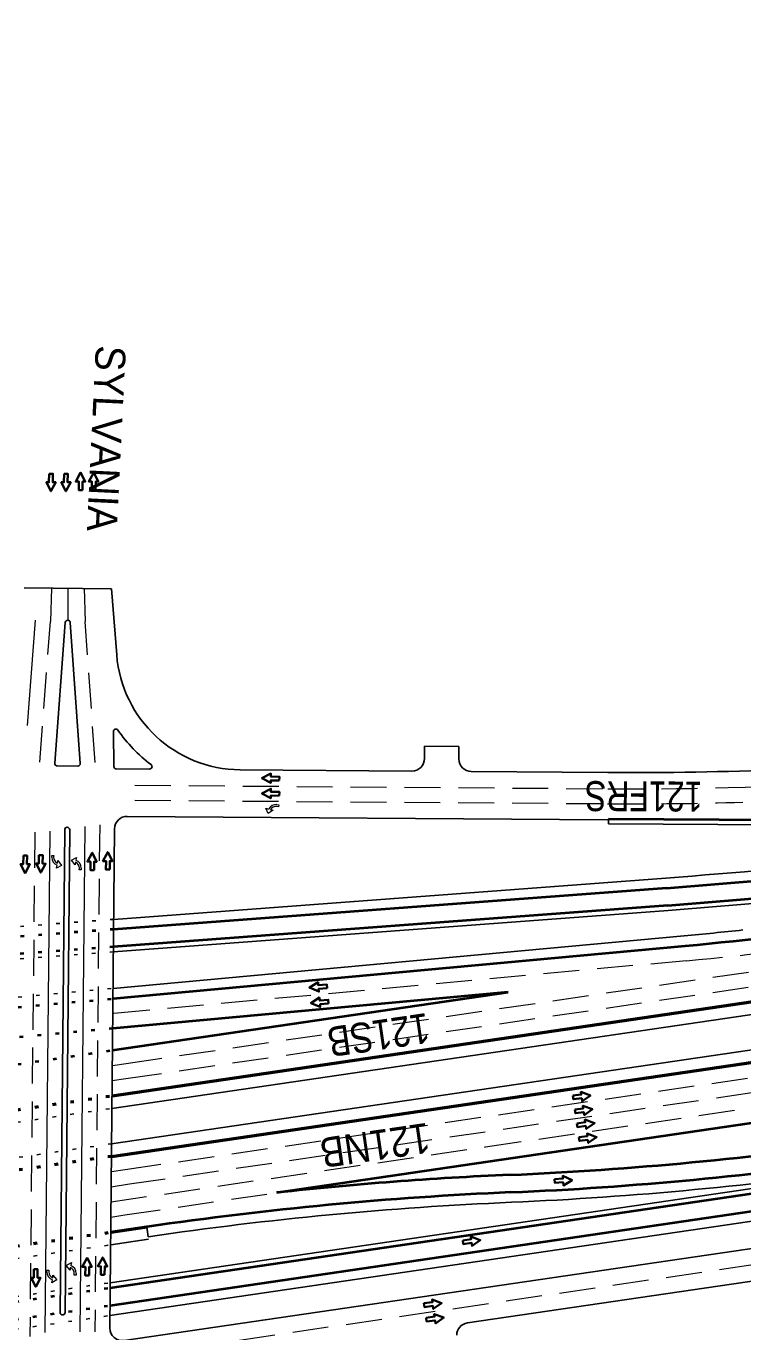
# Model space of a CAD drawing. Extents: x 2329387 to 2347382, y 6951580 to 6987999.
# Drawn here: x 2334845 to 2335420, y 6964774 to 6965820 of the extents above; entities that cross this region are included whole.
import ezdxf

# ---------------------------------------------------------------- set-up
doc = ezdxf.new("R2010")
doc.units = 0
doc.header["$LTSCALE"] = 9.6
doc.linetypes.add('DOTTED', pattern=[1.5, 0.3, -1.2])
doc.linetypes.add('MEDIUM_DASHED', pattern=[4.5, 3, -1.5])
for name, color, linetype, lineweight in [('26', 7, 'Continuous', 53), ('27', 7, 'Continuous', 40), ('28', 7, 'Continuous', 25), ('30', 7, 'Continuous', 13), ('41', 7, 'Continuous', 35), ('50', 7, 'MEDIUM_DASHED', 13)]:
    doc.layers.add(name, color=color, linetype=linetype, lineweight=lineweight)
doc.layers.add('40', color=7, linetype='Continuous')

msp = doc.modelspace()

# ---------------------------------------------------------------- linework, layer by layer
at = {"layer": '26', "lineweight": 25}
for p, q in [((2334914.266, 6964952.715), (2336009.413, 6965113.568)), ((2334913.997, 6964924.375), (2335988.149, 6965082.144)), ((2334913.23, 6964843.404), (2334943.536, 6964847.855))]:
    msp.add_line(p, q, dxfattribs=at)
at = {"layer": '26'}
for p, q in [((2334914.362, 6964962.836), (2336007.96, 6965123.461)), ((2334913.901, 6964914.254), (2335989.602, 6965072.25)), ((2334913.326, 6964853.525), (2334942.083, 6964857.749))]:
    msp.add_line(p, q, dxfattribs=at)
at = {"layer": '26', "linetype": 'DOTTED'}
for p, q in [((2334838.253, 6964951.657), (2334914.362, 6964962.836)), ((2334913.901, 6964914.254), (2334837.792, 6964903.075)), ((2334837.216, 6964842.346), (2334913.326, 6964853.525))]:
    msp.add_line(p, q, dxfattribs=at)
at = {"layer": '26', "linetype": 'DOTTED', "lineweight": 25}
for p, q in [((2334838.157, 6964941.536), (2334914.266, 6964952.715)), ((2334913.997, 6964924.375), (2334837.888, 6964913.196)), ((2334837.12, 6964832.225), (2334913.23, 6964843.404))]:
    msp.add_line(p, q, dxfattribs=at)
at = {"layer": '27', "lineweight": 25}
for p, q in [((2335312.188, 6965180.869), (2335312.216, 6965184.869)), ((2335312.188, 6965180.869), (2335551.616, 6965179.167)), ((2335357.973, 6965137.287), (2334915.703, 6965104.191)), ((2335359.913, 6965111.36), (2334915.455, 6965078.099)), ((2334915.177, 6965048.8), (2335372.828, 6965090.975)), ((2334912.942, 6964813.04), (2335907.743, 6964959.154)), ((2334912.692, 6964786.724), (2335911.521, 6964933.43)), ((2334943.246, 6964849.834), (2334942.083, 6964857.749))]:
    msp.add_line(p, q, dxfattribs=at)
at = {"layer": '27'}
for p, q in [((2335312.216, 6965184.869), (2335551.644, 6965183.167)), ((2335358.57, 6965129.309), (2334915.626, 6965096.163)), ((2335359.614, 6965115.348), (2334915.493, 6965082.113)), ((2334915.101, 6965040.759), (2335373.562, 6965083.009)), ((2334914.708, 6964999.273), (2335231.723, 6965045.836)), ((2335231.724, 6965045.836), (2334914.872, 6965016.636)), ((2334912.903, 6964808.991), (2335908.324, 6964955.196)), ((2335046.491, 6964885.213), (2335519.679, 6964954.714)), ((2334912.769, 6964794.821), (2335910.358, 6964941.345))]:
    msp.add_line(p, q, dxfattribs=at)
at = {"layer": '27', "linetype": 'DOTTED', "lineweight": 25}
for p, q in [((2334915.575, 6965104.181), (2334839.645, 6965098.499)), ((2334915.455, 6965078.099), (2334839.398, 6965072.408)), ((2334839.107, 6965041.79), (2334915.177, 6965048.8)), ((2334836.832, 6964801.861), (2334912.942, 6964813.04)), ((2334836.583, 6964775.545), (2334912.692, 6964786.724))]:
    msp.add_line(p, q, dxfattribs=at)
at = {"layer": '27', "linetype": 'DOTTED'}
for p, q in [((2334915.626, 6965096.163), (2334839.569, 6965090.471)), ((2334915.493, 6965082.113), (2334839.436, 6965076.422)), ((2334839.031, 6965033.749), (2334915.101, 6965040.759)), ((2334914.872, 6965016.636), (2334838.802, 6965009.626)), ((2334838.598, 6964988.094), (2334914.708, 6964999.273)), ((2334836.794, 6964797.812), (2334912.903, 6964808.991)), ((2334836.659, 6964783.642), (2334912.769, 6964794.821))]:
    msp.add_line(p, q, dxfattribs=at)
at = {"layer": '27'}
for centre, radius, start, end in [((2339406.145, 6959556.474), 7976, 170.51466, 170.51466), ((2334931.002, 6970842.912), 5729.578, 274.27965, 282.56422), ((2334931.016, 6970842.915), 5743.578, 274.27952, 282.56422), ((2335110.67, 6967935.71), 2864.789, 275.26524, 278.35573), ((2335109.475, 6967747.539), 2850.789, 272.48994, 278.35573), ((2335109.475, 6967747.539), 2864.789, 272.48994, 278.35573), ((2335358.391, 6962023.37), 2878.789, 92.48994, 96.21987), ((2335358.391, 6962023.37), 2864.789, 92.48994, 98.35573)]:
    msp.add_arc(centre, radius, start, end, dxfattribs=at)
at = {"layer": '27', "lineweight": 25}
for centre, radius, start, end in [((2334931.016, 6970842.915), 5747.578, 274.27952, 282.56422), ((2334931.002, 6970842.912), 5721.578, 274.27965, 281.05479), ((2335110.67, 6967935.71), 2856.789, 275.26524, 276.21166), ((2335109.475, 6967747.539), 2872.789, 272.48994, 278.35573), ((2335358.391, 6962023.37), 2856.789, 92.48994, 98.35573)]:
    msp.add_arc(centre, radius, start, end, dxfattribs=at)
at = {"layer": '28'}
for p, q in [((2334844.028, 6965369.845), (2334913.874, 6965369.183)), ((2334913.874, 6965369.183), (2334918.071, 6965316.163)), ((2334868.45, 6965229.292), (2334876.897, 6965342.082)), ((2334888.849, 6965229.162), (2334880.886, 6965342.074)), ((2334915.372, 6965254.699), (2334915.738, 6965226.766)), ((2335164.654, 6965233.124), (2335164.569, 6965242.964)), ((2335164.569, 6965242.964), (2335192.181, 6965242.759)), ((2335192.162, 6965232.704), (2335192.181, 6965242.759)), ((2334870.43, 6965227.143), (2334886.839, 6965227.021)), ((2334917.723, 6965224.792), (2334944.356, 6965224.595)), ((2335017.018, 6965224.057), (2335154.58, 6965223.037)), ((2335202.088, 6965222.685), (2335311.601, 6965221.874)), ((2334926.465, 6965186.727), (2335311.251, 6965183.876)), ((2334916.391, 6965176.822), (2334912.596, 6964776.65)), ((2334876.382, 6965176.018), (2334872.714, 6964789.25)), ((2334880.382, 6965175.98), (2334876.714, 6964789.212)), ((2334924.049, 6964766.661), (2335903.212, 6964910.479)), ((2335199.022, 6964780.77), (2335447.877, 6964817.321))]:
    msp.add_line(p, q, dxfattribs=at)
at = {"layer": '28', "lineweight": 13}
for p, q in [((2334846.657, 6965259.654), (2334852.964, 6965343.874)), ((2334892.408, 6965178.699), (2334888.568, 6964773.707)), ((2334864.37, 6965174.804), (2334860.561, 6964773.144))]:
    msp.add_line(p, q, dxfattribs=at)
at = {"layer": '28'}
for centre, radius, start, end in [((2334878.891, 6965341.933), 2, 4.0341, 175.71736), ((2335017.759, 6965324.054), 100, 184.52601, 269.57549), ((2334917.372, 6965254.725), 2, 34.62947, 180.74982), ((2335017.759, 6965324.054), 120, 214.62947, 233.01983), ((2334870.445, 6965229.143), 2, 175.71736, 269.57549), ((2334886.854, 6965229.021), 2, 269.57548, 4.0341), ((2335154.654, 6965233.037), 10, 269.57548, 0.4958), ((2335202.162, 6965232.685), 10, 179.89196, 269.57549), ((2334917.738, 6965226.792), 2, 180.74982, 269.57548), ((2334944.371, 6965226.595), 2, 269.57549, 53.01983), ((2335332.828, 6968085.584), 2863.789, 269.57532, 272.39154), ((2334926.391, 6965176.727), 10, 89.57549, 179.45667), ((2334878.382, 6965175.999), 2, 359.45667, 179.44779), ((2335332.828, 6968085.584), 2901.789, 269.57526, 269.59288), ((2334874.714, 6964789.231), 2, 179.45667, 279.94226), ((2334874.714, 6964789.231), 2, 279.94226, 359.45667), ((2335200.475, 6964770.876), 10, 98.35573, 179.586), ((2334922.596, 6964776.555), 10, 179.45667, 278.35573)]:
    msp.add_arc(centre, radius, start, end, dxfattribs=at)
at = {"layer": '30'}
for points in [[(2335039.34, 6965188.928), (2335037.577, 6965193.236), (2335039.761, 6965192.441)], [(2335041.253, 6965191.93), (2335043.399, 6965191.684), (2335039.34, 6965188.928)], [(2335046.49, 6965196.201), (2335047.921, 6965196.041), (2335047.744, 6965194.491), (2335046.481, 6965194.635)], [(2334865.988, 6965153.925), (2334866.016, 6965155.365), (2334867.576, 6965155.331), (2334867.549, 6965154.06)], [(2334873.887, 6965147.473), (2334869.759, 6965145.322), (2334870.35, 6965147.569)], [(2334870.722, 6965149.102), (2334870.77, 6965151.261), (2334873.887, 6965147.473)], [(2334881.767, 6965151.704), (2334885.882, 6965153.879), (2334885.304, 6965151.628)], [(2334884.941, 6965150.093), (2334884.906, 6965147.934), (2334881.767, 6965151.704)], [(2334889.703, 6965145.298), (2334889.683, 6965143.858), (2334888.123, 6965143.883), (2334888.143, 6965145.154)], [(2334862.147, 6964821.622), (2334862.167, 6964823.062), (2334863.727, 6964823.037), (2334863.707, 6964821.766)], [(2334877.701, 6964826.93), (2334881.816, 6964829.105), (2334881.238, 6964826.854)], [(2334880.875, 6964825.319), (2334880.84, 6964823.16), (2334877.701, 6964826.93)], [(2334885.637, 6964820.524), (2334885.617, 6964819.084), (2334884.057, 6964819.109), (2334884.077, 6964820.38)], [(2334870.083, 6964815.216), (2334865.968, 6964813.041), (2334866.546, 6964815.292)], [(2334866.909, 6964816.827), (2334866.944, 6964818.986), (2334870.083, 6964815.216)]]:
    msp.add_lwpolyline(points, dxfattribs=at)
for centre, radius, start, end in [((2335045.881, 6965189.389), 6.84, 84.88871, 153.49732), ((2335045.881, 6965189.389), 5.28, 83.4878, 151.23854), ((2334872.828, 6965153.945), 6.84, 180.15285, 248.76146), ((2334872.828, 6965153.945), 5.28, 178.75193, 246.50267), ((2334882.864, 6965145.24), 5.28, 359.08516, 66.8359), ((2334882.864, 6965145.24), 6.84, 0.48608, 69.09469), ((2334868.987, 6964821.68), 6.84, 180.48608, 249.09469), ((2334868.987, 6964821.68), 5.28, 179.08516, 246.8359), ((2334878.797, 6964820.466), 5.28, 359.08516, 66.8359), ((2334878.797, 6964820.466), 6.84, 0.48608, 69.09469)]:
    msp.add_arc(centre, radius, start, end, dxfattribs=at)
at = {"layer": '41'}
for points in [[(2334863.915, 6965461.31), (2334866.915, 6965461.264), (2334866.811, 6965454.458), (2334869.248, 6965454.42), (2334865.36, 6965447.279), (2334861.691, 6965454.536), (2334863.811, 6965454.504)], [(2334875.879, 6965461.31), (2334878.88, 6965461.264), (2334878.776, 6965454.458), (2334881.213, 6965454.42), (2334877.324, 6965447.279), (2334873.656, 6965454.536), (2334875.775, 6965454.504)], [(2334890.685, 6965448.206), (2334887.685, 6965448.234), (2334887.749, 6965455.041), (2334885.312, 6965455.064), (2334889.159, 6965462.228), (2334892.869, 6965454.992), (2334890.75, 6965455.012)], [(2334901.154, 6965448.206), (2334898.154, 6965448.234), (2334898.218, 6965455.041), (2334895.781, 6965455.064), (2334899.628, 6965462.228), (2334903.338, 6965454.992), (2334901.219, 6965455.012)], [(2335048.361, 6965215.492), (2335048.409, 6965218.492), (2335041.603, 6965218.601), (2335041.642, 6965221.038), (2335034.382, 6965217.374), (2335041.521, 6965213.481), (2335041.555, 6965215.601)], [(2335048.341, 6965203.272), (2335048.389, 6965206.273), (2335041.583, 6965206.381), (2335041.622, 6965208.818), (2335034.362, 6965205.155), (2335041.501, 6965201.262), (2335041.535, 6965203.381)], [(2334843.258, 6965155.282), (2334846.259, 6965155.236), (2334846.155, 6965148.43), (2334848.592, 6965148.393), (2334844.703, 6965141.252), (2334841.035, 6965148.509), (2334843.154, 6965148.476)], [(2334855.759, 6965155.682), (2334858.76, 6965155.636), (2334858.655, 6965148.83), (2334861.092, 6965148.793), (2334857.204, 6965141.651), (2334853.536, 6965148.908), (2334855.655, 6965148.876)], [(2334899.943, 6965143.602), (2334896.942, 6965143.63), (2334897.007, 6965150.437), (2334894.569, 6965150.46), (2334898.416, 6965157.624), (2334902.127, 6965150.388), (2334900.007, 6965150.408)], [(2334912.441, 6965144.074), (2334909.44, 6965144.103), (2334909.505, 6965150.909), (2334907.068, 6965150.932), (2334910.915, 6965158.096), (2334914.625, 6965150.86), (2334912.506, 6965150.881)], [(2335086.636, 6965049.035), (2335086.375, 6965052.024), (2335079.594, 6965051.432), (2335079.382, 6965053.86), (2335072.538, 6965049.47), (2335080.039, 6965046.331), (2335079.855, 6965048.443)], [(2335087.771, 6965036.717), (2335087.51, 6965039.706), (2335080.729, 6965039.114), (2335080.517, 6965041.542), (2335073.673, 6965037.152), (2335081.174, 6965034.013), (2335080.99, 6965036.125)], [(2335283.555, 6964962.95), (2335283.943, 6964959.975), (2335290.693, 6964960.855), (2335291.008, 6964958.438), (2335297.659, 6964963.117), (2335290.03, 6964965.933), (2335290.304, 6964963.831)], [(2335285.174, 6964951.833), (2335285.562, 6964948.857), (2335292.312, 6964949.738), (2335292.627, 6964947.321), (2335299.278, 6964951.999), (2335291.649, 6964954.815), (2335291.923, 6964952.713)], [(2335286.793, 6964940.715), (2335287.181, 6964937.739), (2335293.931, 6964938.62), (2335294.246, 6964936.203), (2335300.897, 6964940.882), (2335293.268, 6964943.697), (2335293.543, 6964941.595)], [(2335288.412, 6964929.597), (2335288.8, 6964926.622), (2335295.55, 6964927.502), (2335295.865, 6964925.085), (2335302.516, 6964929.764), (2335294.888, 6964932.579), (2335295.162, 6964930.478)], [(2335268.814, 6964896.085), (2335268.986, 6964893.089), (2335275.782, 6964893.48), (2335275.922, 6964891.046), (2335282.893, 6964895.232), (2335275.488, 6964898.591), (2335275.61, 6964896.475)], [(2335195.314, 6964846.946), (2335195.702, 6964843.97), (2335202.452, 6964844.851), (2335202.767, 6964842.434), (2335209.418, 6964847.112), (2335201.79, 6964849.928), (2335202.064, 6964847.826)], [(2334895.876, 6964818.828), (2334892.875, 6964818.857), (2334892.94, 6964825.663), (2334890.503, 6964825.686), (2334894.35, 6964832.85), (2334898.06, 6964825.614), (2334895.941, 6964825.634)], [(2334908.374, 6964819.3), (2334905.374, 6964819.329), (2334905.438, 6964826.135), (2334903.001, 6964826.158), (2334906.848, 6964833.322), (2334910.558, 6964826.087), (2334908.439, 6964826.107)], [(2334851.693, 6964823.768), (2334854.694, 6964823.739), (2334854.629, 6964816.933), (2334857.067, 6964816.91), (2334853.22, 6964809.746), (2334849.509, 6964816.982), (2334851.629, 6964816.961)], [(2335164.276, 6964796.523), (2335164.664, 6964793.547), (2335171.414, 6964794.428), (2335171.729, 6964792.011), (2335178.38, 6964796.689), (2335170.751, 6964799.505), (2335171.026, 6964797.403)], [(2335165.978, 6964784.935), (2335166.366, 6964781.959), (2335173.116, 6964782.84), (2335173.431, 6964780.423), (2335180.082, 6964785.101), (2335172.453, 6964787.917), (2335172.728, 6964785.815)]]:
    msp.add_lwpolyline(points, close=True, dxfattribs=at)
at = {"layer": '50'}
for p, q in [((2334865.951, 6965369.542), (2334864.93, 6965342.978)), ((2334891.951, 6965369.486), (2334892.856, 6965342.918)), ((2334856.484, 6965230.188), (2334864.93, 6965342.978)), ((2334900.82, 6965230.006), (2334892.856, 6965342.918)), ((2334932.687, 6965211.681), (2335311.505, 6965208.874)), ((2334932.572, 6965199.682), (2335311.413, 6965196.875)), ((2334904.421, 6965179.968), (2334900.568, 6964773.666)), ((2334852.363, 6965174.168), (2334848.529, 6964769.826)), ((2334925.608, 6964988.745), (2336004.472, 6965147.207)), ((2334925.493, 6964976.6), (2336006.216, 6965135.334)), ((2335374.663, 6965071.059), (2334914.987, 6965028.698)), ((2334924.802, 6964903.726), (2335991.346, 6965060.377)), ((2334928.405, 6964892.126), (2335993.089, 6965048.505)), ((2335213.626, 6964921.89), (2335994.833, 6965036.632)), ((2334914.592, 6964987.127), (2334925.608, 6964988.745)), ((2334914.477, 6964974.982), (2334925.493, 6964976.6)), ((2334913.556, 6964877.817), (2335213.626, 6964921.89)), ((2334913.786, 6964902.108), (2334924.802, 6964903.726)), ((2334930.91, 6964754.53), (2335905.116, 6964897.619)), ((2334913.671, 6964889.962), (2334928.405, 6964892.126)), ((2334924.457, 6964867.289), (2335046.491, 6964885.213)), ((2334913.441, 6964865.671), (2334924.457, 6964867.289))]:
    msp.add_line(p, q, dxfattribs=at)
at = {"layer": '50', "linetype": 'Continuous'}
msp.add_line((2334878.951, 6965369.514), (2334878.895, 6965343.933), dxfattribs=at)
at = {"layer": '50'}
for centre, radius, start, end in [((2335332.828, 6968085.584), 2876.789, 269.57533, 278.35561), ((2335332.828, 6968085.584), 2888.789, 269.57526, 271.72504), ((2335110.67, 6967935.71), 2876.789, 275.26524, 278.35573)]:
    msp.add_arc(centre, radius, start, end, dxfattribs=at)

# ---------------------------------------------------------------- texts
at = {"layer": '40'}
for s, rotation, width, p in [('SYLVANIA', 267.209, 0.95, (2334901.442, 6965564.567)), ('121FRS', 179.738, 0.8, (2335387.486, 6965214.569)), ('121SB', 188.368, 0.85, (2335166.626, 6965029.295)), ('121NB', 188.321, 0.9, (2335167.09, 6964941.283))]:
    msp.add_text(s, height=24, rotation=rotation, dxfattribs=dict(at, width=width)).set_placement(p)

doc.saveas('drawing.dxf')
